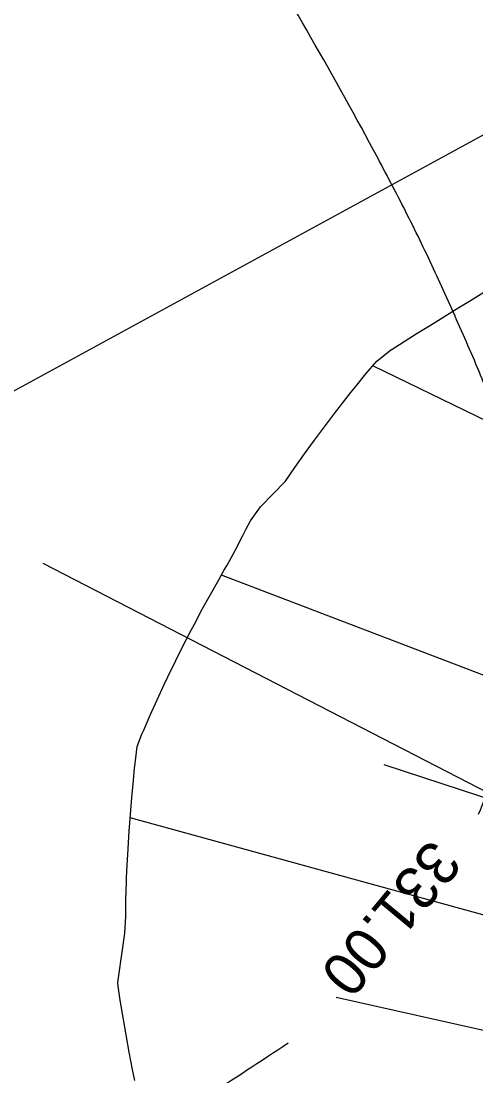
# Model space of a CAD drawing. Extents: x -564037 to -563827, y -1163561 to -1163412.
# Drawn here: x -563871.67 to -563866.4, y -1163500.35 to -1163488.1 of the extents above; entities that cross this region are included whole.
import ezdxf

# ---------------------------------------------------------------- set-up
doc = ezdxf.new("R2010")
doc.units = 0
for name, color, linetype in [('5', 7, 'Continuous'), ('Line', 7, 'Continuous'), ('Vrstva 24', 7, 'Continuous'), ('Vrstva 25', 7, 'Continuous'), ('Vrstva 26', 7, 'Continuous')]:
    doc.layers.add(name, color=color, linetype=linetype)

msp = doc.modelspace()

# ---------------------------------------------------------------- linework, layer by layer
msp.add_lwpolyline([(-563870.356, -1163500.406), (-563870.382, -1163500.275), (-563870.42, -1163500.075), (-563870.457, -1163499.874), (-563870.491, -1163499.672), (-563870.524, -1163499.47), (-563870.549, -1163499.308), (-563870.552, -1163499.268), (-563870.526, -1163499.077), (-563870.522, -1163499.047), (-563870.499, -1163498.886), (-563870.469, -1163498.695), (-563870.461, -1163498.499), (-563870.458, -1163498.302), (-563870.452, -1163498.104), (-563870.45, -1163498.053), (-563870.444, -1163497.906), (-563870.434, -1163497.716), (-563870.434, -1163497.709), (-563870.421, -1163497.511), (-563870.407, -1163497.314), (-563870.39, -1163497.117), (-563870.371, -1163496.92), (-563870.357, -1163496.779), (-563870.35, -1163496.723), (-563870.327, -1163496.526), (-563870.273, -1163496.384), (-563870.256, -1163496.344), (-563870.177, -1163496.164), (-563870.097, -1163495.985), (-563870.014, -1163495.807), (-563869.93, -1163495.63), (-563869.915, -1163495.6), (-563869.843, -1163495.454), (-563869.755, -1163495.279), (-563869.702, -1163495.177), (-563869.664, -1163495.105), (-563869.572, -1163494.933), (-563869.477, -1163494.761), (-563869.381, -1163494.59), (-563869.32, -1163494.483), (-563869.283, -1163494.421), (-563869.19, -1163494.249), (-563869.102, -1163494.077), (-563869.066, -1163494.008), (-563869.011, -1163493.905), (-563868.898, -1163493.743), (-563868.754, -1163493.595), (-563868.609, -1163493.448), (-563868.599, -1163493.434), (-563868.498, -1163493.287), (-563868.385, -1163493.128), (-563868.27, -1163492.97), (-563868.246, -1163492.937), (-563868.154, -1163492.813), (-563868.036, -1163492.658), (-563867.916, -1163492.504), (-563867.85, -1163492.42), (-563867.795, -1163492.351), (-563867.672, -1163492.2), (-563867.547, -1163492.05), (-563867.383, -1163491.921), (-563867.379, -1163491.919), (-563867.23, -1163491.824), (-563867.077, -1163491.728), (-563866.923, -1163491.632), (-563866.769, -1163491.536), (-563866.615, -1163491.441), (-563866.46, -1163491.346), (-563866.305, -1163491.251)])
at = {"layer": '5'}
for p, q in [((-563897.15, -1163506.247), (-563862.812, -1163487.513)), ((-563871.424, -1163494.398), (-563841.172, -1163509.993))]:
    msp.add_line(p, q, dxfattribs=at)
at = {"layer": 'Line'}
for p, q in [((-563863.457, -1163494.115), (-563867.593, -1163492.106)), ((-563864.459, -1163496.404), (-563869.35, -1163494.536)), ((-563867.464, -1163496.734), (-563864.877, -1163497.582)), ((-563865.238, -1163498.779), (-563870.41, -1163497.354)), ((-563868.019, -1163499.435), (-563865.541, -1163499.991))]:
    msp.add_line(p, q, dxfattribs=at)
at = {"layer": 'Vrstva 24'}
for points in [[(-563866.364, -1163497.311), (-563866.075, -1163496.511), (-563865.895, -1163495.533), (-563865.845, -1163494.553), (-563865.947, -1163493.507), (-563866.272, -1163492.388), (-563866.563, -1163491.699), (-563866.868, -1163491.02), (-563867.192, -1163490.352), (-563867.536, -1163489.691), (-563869.125, -1163486.92), (-563869.85, -1163485.772), (-563870.624, -1163484.653), (-563871.666, -1163483.346), (-563872.824, -1163482.142), (-563874.562, -1163480.618), (-563875.472, -1163479.893), (-563878.363, -1163477.556), (-563882.755, -1163474.046), (-563884.234, -1163472.969), (-563885.61, -1163472.026), (-563886.998, -1163471.1), (-563889.83, -1163469.34), (-563892.347, -1163467.891)], [(-563852.947, -1163500.287), (-563852.983, -1163499.934), (-563853.278, -1163497.907), (-563853.324, -1163497.501), (-563853.384, -1163496.604), (-563853.408, -1163496.155), (-563853.449, -1163495.707), (-563853.76, -1163494.797), (-563854.364, -1163493.737), (-563856.816, -1163489.636), (-563859.313, -1163485.439), (-563859.915, -1163484.694), (-563860.397, -1163484.207), (-563862.509, -1163482.09), (-563867.011, -1163477.664), (-563868.116, -1163476.702), (-563871.116, -1163474.41), (-563872.986, -1163473.06), (-563873.689, -1163472.566), (-563878.103, -1163469.411), (-563878.316, -1163469.26)], [(-563905.221, -1163519.388), (-563901.417, -1163517.444), (-563900.291, -1163516.907), (-563895.909, -1163514.815), (-563892.135, -1163512.984), (-563890.63, -1163512.267), (-563888.864, -1163511.357), (-563887.99, -1163510.869), (-563887.125, -1163510.367), (-563886.26, -1163509.866), (-563885.383, -1163509.384), (-563882.362, -1163507.826), (-563880.585, -1163506.938), (-563878.549, -1163505.818), (-563872.848, -1163502.599), (-563870.632, -1163501.288), (-563869.542, -1163500.601), (-563868.575, -1163499.969)]]:
    msp.add_spline(points, degree=3, dxfattribs=at)
at = {"layer": 'Vrstva 26'}
for points in [[(-563859.41, -1163497.306), (-563859.213, -1163496.32), (-563859.173, -1163495.343), (-563859.23, -1163495.062), (-563859.315, -1163494.786), (-563859.559, -1163494.264), (-563860.664, -1163492.33), (-563861.767, -1163490.395), (-563863.612, -1163487.077), (-563864.619, -1163485.435), (-563865.167, -1163484.642), (-563865.744, -1163483.864), (-563868.01, -1163481.46), (-563871.348, -1163478.665), (-563874.529, -1163476.131), (-563879.25, -1163472.365), (-563881.038, -1163471.025), (-563881.839, -1163470.479), (-563883.542, -1163469.415), (-563886.341, -1163467.718)], [(-563846.143, -1163505.119), (-563846.16, -1163504.298), (-563846.784, -1163499.435), (-563846.859, -1163499.141), (-563847.15, -1163498.47), (-563847.685, -1163497.291), (-563847.809, -1163497.032), (-563850.257, -1163492.396), (-563853.06, -1163487.093), (-563853.131, -1163486.997), (-563856.933, -1163483.04), (-563859.434, -1163480.56), (-563863.484, -1163476.533), (-563865.168, -1163474.917), (-563866.123, -1163474.143), (-563868.988, -1163472.112)]]:
    msp.add_spline(points, degree=3, dxfattribs=at)

# ---------------------------------------------------------------- texts
at = {"layer": 'Vrstva 25'}
msp.add_text('331.00', height=0.5, rotation=230.2626, dxfattribs=at).set_placement((-563866.917, -1163497.579))

doc.saveas('drawing.dxf')
